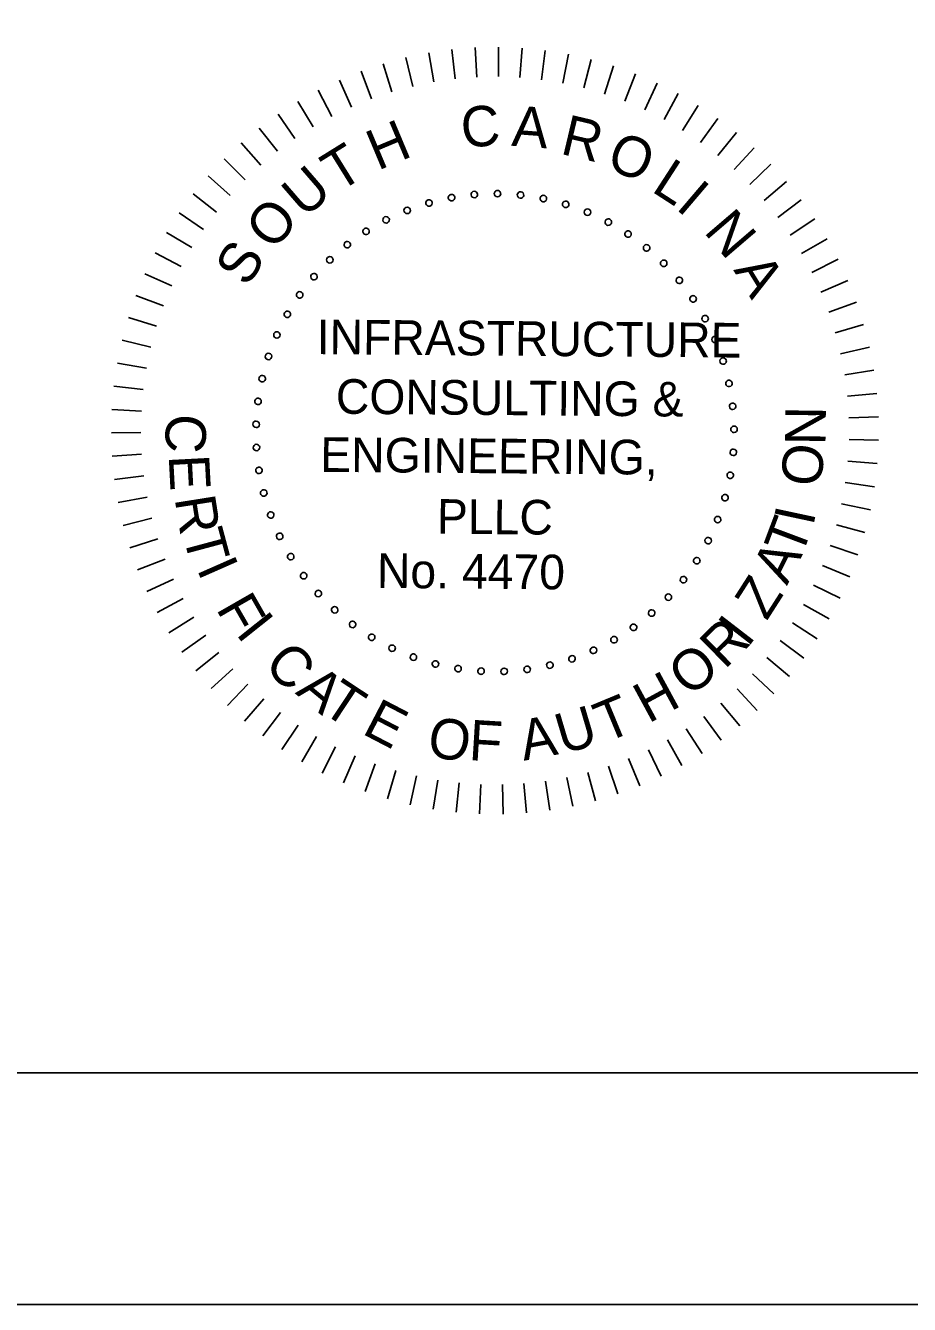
# Model space of a CAD drawing. Extents: x -125.5 to -89.4, y -5.1 to 16.9.
# Drawn here: x -100.213 to -98.306, y -5.066 to -2.306 of the extents above; entities that cross this region are included whole.
import ezdxf

# ---------------------------------------------------------------- set-up
doc = ezdxf.new("R2010")
doc.units = 0
for name, color, linetype in [('BR_BORDER LINES', 7, 'Continuous'), ('BR_TEXT', 7, 'Continuous'), ('Level 31', 7, 'Continuous')]:
    doc.layers.add(name, color=color, linetype=linetype)

msp = doc.modelspace()

# ---------------------------------------------------------------- linework, layer by layer
at = {"layer": 'BR_BORDER LINES'}
msp.add_line((-123.6994, -4.5662), (-90.0334, -4.5662), dxfattribs=at)
at = {"layer": 'BR_TEXT'}
for p, q in [((-99.343, -2.3651), (-99.332, -2.4278)), ((-99.2931, -2.3579), (-99.2858, -2.4212)), ((-99.2427, -2.3538), (-99.2394, -2.4174)), ((-99.1923, -2.3527), (-99.1928, -2.4164)), ((-99.1418, -2.3548), (-99.1462, -2.4183)), ((-99.0916, -2.3599), (-99.0999, -2.423)), ((-99.0418, -2.368), (-99.0539, -2.4305)), ((-99.4412, -2.3886), (-99.4226, -2.4495)), ((-99.3925, -2.3754), (-99.3776, -2.4373)), ((-98.9925, -2.3792), (-99.0084, -2.4408)), ((-98.9441, -2.3933), (-98.9637, -2.4539)), ((-99.5358, -2.4238), (-99.5099, -2.482)), ((-99.489, -2.4048), (-99.4667, -2.4644)), ((-98.8966, -2.4104), (-98.9199, -2.4696)), ((-99.5813, -2.4457), (-99.5519, -2.5022)), ((-98.8502, -2.4303), (-98.877, -2.488)), ((-98.8051, -2.453), (-98.8354, -2.509)), ((-99.6253, -2.4703), (-99.5926, -2.5249)), ((-98.7615, -2.4785), (-98.7952, -2.5325)), ((-99.6678, -2.4975), (-99.6318, -2.55)), ((-98.7195, -2.5065), (-98.7564, -2.5584)), ((-99.7086, -2.5273), (-99.6694, -2.5775)), ((-98.6793, -2.5371), (-98.7193, -2.5866)), ((-99.7475, -2.5595), (-99.7053, -2.6072)), ((-99.7843, -2.5941), (-99.7393, -2.6391)), ((-98.6411, -2.57), (-98.684, -2.617)), ((-98.6049, -2.6052), (-98.6506, -2.6495)), ((-99.819, -2.6308), (-99.7713, -2.673)), ((-98.571, -2.6426), (-98.6193, -2.684)), ((-99.8513, -2.6695), (-99.8012, -2.7087)), ((-98.5393, -2.6819), (-98.5901, -2.7204)), ((-99.8813, -2.7102), (-99.8288, -2.7463)), ((-98.5102, -2.7232), (-98.5632, -2.7584)), ((-99.9087, -2.7526), (-99.8541, -2.7854)), ((-98.4836, -2.7661), (-98.5387, -2.798)), ((-99.9334, -2.7965), (-99.877, -2.826)), ((-98.4597, -2.8105), (-98.5166, -2.839)), ((-99.9555, -2.842), (-99.8973, -2.8679)), ((-98.4385, -2.8563), (-98.497, -2.8813)), ((-99.9747, -2.8886), (-99.9151, -2.911)), ((-98.4202, -2.9034), (-98.4801, -2.9248)), ((-99.991, -2.9364), (-99.9302, -2.9551)), ((-98.4047, -2.9514), (-98.4659, -2.9691)), ((-100.0044, -2.9851), (-99.9426, -3)), ((-98.3922, -3.0004), (-98.4544, -3.0143)), ((-100.0149, -3.0345), (-99.9522, -3.0456)), ((-98.3828, -3.05), (-98.4456, -3.0601)), ((-100.0222, -3.0844), (-99.959, -3.0917)), ((-98.3763, -3.1), (-98.4397, -3.1063)), ((-100.0266, -3.1347), (-99.963, -3.1382)), ((-98.373, -3.1504), (-98.4366, -3.1528)), ((-100.0278, -3.1852), (-99.9641, -3.1847)), ((-98.3727, -3.2009), (-98.4363, -3.1994)), ((-100.026, -3.2356), (-99.9625, -3.2313)), ((-98.3755, -3.2513), (-98.4389, -3.2459)), ((-100.0211, -3.2859), (-99.9579, -3.2777)), ((-98.3813, -3.3014), (-98.4443, -3.2922)), ((-100.0131, -3.3357), (-99.9506, -3.3237)), ((-98.3902, -3.3511), (-98.4525, -3.3381)), ((-100.0021, -3.385), (-99.9405, -3.3692)), ((-98.4021, -3.4002), (-98.4635, -3.3834)), ((-99.9882, -3.4335), (-99.9276, -3.414)), ((-98.417, -3.4484), (-98.4773, -3.4279)), ((-99.9713, -3.4811), (-99.912, -3.4579)), ((-98.4348, -3.4957), (-98.4937, -3.4715)), ((-99.9515, -3.5276), (-99.8937, -3.5008)), ((-98.4554, -3.5417), (-98.5128, -3.514)), ((-99.929, -3.5727), (-99.8729, -3.5425)), ((-98.4789, -3.5865), (-98.5344, -3.5553)), ((-99.9037, -3.6164), (-99.8496, -3.5828)), ((-98.505, -3.6297), (-98.5585, -3.5952)), ((-99.8758, -3.6585), (-99.8239, -3.6217)), ((-98.5336, -3.6712), (-98.5849, -3.6335)), ((-99.8454, -3.6988), (-99.7958, -3.6589)), ((-98.5648, -3.7109), (-98.6137, -3.6702)), ((-99.8126, -3.7372), (-99.7655, -3.6943)), ((-98.5983, -3.7487), (-98.6447, -3.705)), ((-99.7775, -3.7735), (-99.7331, -3.7278)), ((-98.6341, -3.7843), (-98.6777, -3.7379)), ((-99.7403, -3.8076), (-99.6988, -3.7593)), ((-98.672, -3.8177), (-98.7126, -3.7687)), ((-99.701, -3.8393), (-99.6626, -3.7886)), ((-98.7118, -3.8487), (-98.7494, -3.7974)), ((-99.6599, -3.8687), (-99.6246, -3.8157)), ((-98.7534, -3.8772), (-98.7879, -3.8237)), ((-99.6171, -3.8954), (-99.5851, -3.8404)), ((-99.5728, -3.9195), (-99.5442, -3.8626)), ((-98.7967, -3.9032), (-98.8278, -3.8476)), ((-99.527, -3.9408), (-99.5019, -3.8823)), ((-98.8877, -3.9469), (-98.9118, -3.888)), ((-98.8416, -3.9264), (-98.8692, -3.8691)), ((-99.48, -3.9594), (-99.4586, -3.8994)), ((-99.432, -3.975), (-99.4143, -3.9138)), ((-98.9833, -3.9792), (-99.0001, -3.9178)), ((-98.935, -3.9645), (-98.9555, -3.9042)), ((-99.3832, -3.9876), (-99.3692, -3.9255)), ((-99.3336, -3.9973), (-99.3234, -3.9344)), ((-99.2836, -4.0039), (-99.2772, -3.9406)), ((-99.2332, -4.0075), (-99.2307, -3.9438)), ((-99.1827, -4.0079), (-99.1841, -3.9443)), ((-99.1323, -4.0053), (-99.1376, -3.9419)), ((-99.0821, -3.9997), (-99.0913, -3.9367)), ((-99.0324, -3.991), (-99.0454, -3.9286))]:
    msp.add_line(p, q, dxfattribs=at)
for centre, start, end in [((-99.2939, -2.6775), 10.6038, 190.6038), ((-99.2939, -2.6775), 190.6038, 10.6038), ((-99.2445, -2.6708), 5.0653, 185.0653), ((-99.2445, -2.6708), 185.0653, 5.0653), ((-99.1947, -2.6689), 359.5268, 179.5268), ((-99.1947, -2.6689), 179.5268, 359.5268), ((-99.145, -2.6718), 173.9884, 353.9884), ((-99.145, -2.6718), 353.9884, 173.9884), ((-99.0957, -2.6795), 348.4499, 168.4499), ((-99.3896, -2.705), 21.6807, 201.6807), ((-99.3896, -2.705), 201.6807, 21.6807), ((-99.3424, -2.6889), 16.1422, 196.1422), ((-99.3424, -2.6889), 196.1422, 16.1422), ((-99.0957, -2.6795), 168.4499, 348.4499), ((-99.0475, -2.6919), 162.9114, 342.9114), ((-99.0475, -2.6919), 342.9114, 162.9114), ((-99.0006, -2.709), 337.373, 157.373), ((-99.435, -2.7255), 27.2191, 207.2191), ((-99.435, -2.7255), 207.2191, 27.2191), ((-99.0006, -2.709), 157.373, 337.373), ((-98.9557, -2.7304), 151.8345, 331.8345), ((-98.9557, -2.7304), 331.8345, 151.8345), ((-99.4782, -2.7503), 32.7576, 212.7576), ((-99.4782, -2.7503), 212.7576, 32.7576), ((-98.913, -2.7561), 146.2961, 326.2961), ((-98.913, -2.7561), 326.2961, 146.2961), ((-99.5188, -2.7792), 38.2961, 218.2961), ((-99.5188, -2.7792), 218.2961, 38.2961), ((-98.873, -2.7858), 140.7576, 320.7576), ((-98.873, -2.7858), 320.7576, 140.7576), ((-99.5564, -2.8119), 43.8345, 223.8345), ((-99.5564, -2.8119), 223.8345, 43.8345), ((-98.836, -2.8192), 135.2191, 315.2191), ((-98.836, -2.8192), 315.2191, 135.2191), ((-99.5907, -2.848), 49.373, 229.373), ((-99.5907, -2.848), 229.373, 49.373), ((-98.8024, -2.8561), 129.6807, 309.6807), ((-98.8024, -2.8561), 309.6807, 129.6807), ((-99.6214, -2.8873), 54.9114, 234.9114), ((-99.6214, -2.8873), 234.9114, 54.9114), ((-98.7726, -2.896), 124.1422, 304.1422), ((-98.7726, -2.896), 304.1422, 124.1422), ((-99.6481, -2.9293), 60.4499, 240.4499), ((-99.6481, -2.9293), 240.4499, 60.4499), ((-98.7467, -2.9386), 118.6038, 298.6038), ((-98.7467, -2.9386), 298.6038, 118.6038), ((-99.6706, -2.9738), 65.9884, 245.9884), ((-99.6706, -2.9738), 245.9884, 65.9884), ((-98.7251, -2.9835), 113.0653, 293.0653), ((-98.7251, -2.9835), 293.0653, 113.0653), ((-99.6888, -3.0202), 71.5268, 251.5268), ((-99.6888, -3.0202), 251.5268, 71.5268), ((-98.7079, -3.0302), 107.5268, 287.5268), ((-98.7079, -3.0302), 287.5268, 107.5268), ((-99.7024, -3.0681), 77.0653, 257.0653), ((-99.7024, -3.0681), 257.0653, 77.0653), ((-98.6953, -3.0785), 101.9884, 281.9884), ((-98.6953, -3.0785), 281.9884, 101.9884), ((-99.7113, -3.1172), 82.6038, 262.6038), ((-99.7113, -3.1172), 262.6038, 82.6038), ((-98.6874, -3.1277), 96.4499, 276.4499), ((-98.6874, -3.1277), 276.4499, 96.4499), ((-99.7154, -3.1668), 88.1422, 268.1422), ((-99.7154, -3.1668), 268.1422, 88.1422), ((-98.6843, -3.1774), 90.9114, 270.9114), ((-98.6843, -3.1774), 270.9114, 90.9114), ((-99.7147, -3.2167), 93.6807, 273.6807), ((-99.7147, -3.2167), 273.6807, 93.6807), ((-98.686, -3.2272), 85.373, 265.373), ((-98.686, -3.2272), 265.373, 85.373), ((-99.7092, -3.2662), 99.2191, 279.2191), ((-99.7092, -3.2662), 279.2191, 99.2191), ((-98.6926, -3.2766), 79.8345, 259.8345), ((-98.6926, -3.2766), 259.8345, 79.8345), ((-99.6989, -3.3149), 104.7576, 284.7576), ((-99.6989, -3.3149), 284.7576, 104.7576), ((-98.7038, -3.3251), 74.2961, 254.2961), ((-98.7038, -3.3251), 254.2961, 74.2961), ((-99.684, -3.3625), 110.2961, 290.2961), ((-99.684, -3.3625), 290.2961, 110.2961), ((-98.7197, -3.3724), 68.7576, 248.7576), ((-98.7197, -3.3724), 248.7576, 68.7576), ((-99.6646, -3.4084), 115.8345, 295.8345), ((-99.6646, -3.4084), 295.8345, 115.8345), ((-98.7401, -3.4178), 63.2191, 243.2191), ((-98.7401, -3.4178), 243.2191, 63.2191), ((-99.6408, -3.4522), 121.373, 301.373), ((-99.6408, -3.4522), 301.373, 121.373), ((-98.7647, -3.4611), 57.6807, 237.6807), ((-98.7647, -3.4611), 237.6807, 57.6807), ((-99.6129, -3.4935), 126.9114, 306.9114), ((-99.6129, -3.4935), 306.9114, 126.9114), ((-98.7934, -3.5019), 52.1422, 232.1422), ((-98.7934, -3.5019), 232.1422, 52.1422), ((-99.5812, -3.5319), 132.4499, 312.4499), ((-99.5812, -3.5319), 312.4499, 132.4499), ((-98.826, -3.5396), 46.6038, 226.6038), ((-99.5459, -3.5671), 317.9884, 137.9884), ((-98.826, -3.5396), 226.6038, 46.6038), ((-99.5459, -3.5671), 137.9884, 317.9884), ((-98.862, -3.5741), 41.0653, 221.0653), ((-98.862, -3.5741), 221.0653, 41.0653), ((-99.5074, -3.5987), 143.5268, 323.5268), ((-99.5074, -3.5987), 323.5268, 143.5268), ((-98.9012, -3.6049), 35.5268, 215.5268), ((-98.9012, -3.6049), 215.5268, 35.5268), ((-99.466, -3.6264), 149.0653, 329.0653), ((-99.466, -3.6264), 329.0653, 149.0653), ((-99.4221, -3.65), 334.6038, 154.6038), ((-98.9431, -3.6317), 29.9884, 209.9884), ((-98.9431, -3.6317), 209.9884, 29.9884), ((-99.4221, -3.65), 154.6038, 334.6038), ((-99.3761, -3.6693), 160.1422, 340.1422), ((-99.3761, -3.6693), 340.1422, 160.1422), ((-99.0338, -3.6728), 18.9114, 198.9114), ((-99.0338, -3.6728), 198.9114, 18.9114), ((-98.9875, -3.6545), 24.4499, 204.4499), ((-98.9875, -3.6545), 204.4499, 24.4499), ((-99.3285, -3.684), 165.6807, 345.6807), ((-99.3285, -3.684), 345.6807, 165.6807), ((-99.2797, -3.6941), 351.2191, 171.2191), ((-99.2797, -3.6941), 171.2191, 351.2191), ((-99.2302, -3.6994), 356.7576, 176.7576), ((-99.1803, -3.6999), 2.2961, 182.2961), ((-99.1307, -3.6956), 7.8345, 187.8345), ((-99.1307, -3.6956), 187.8345, 7.8345), ((-99.0817, -3.6865), 13.373, 193.373), ((-99.0817, -3.6865), 193.373, 13.373), ((-99.2302, -3.6994), 176.7576, 356.7576), ((-99.1803, -3.6999), 182.2961, 2.2961)]:
    msp.add_arc(centre, 0.00701, start, end, dxfattribs=at)
at = {"layer": 'Level 31'}
msp.add_lwpolyline([(-125.5328, 16.9339), (-125.5328, -5.0661), (-89.5328, -5.0661), (-89.5328, 16.9339)], dxfattribs=at)

# ---------------------------------------------------------------- texts
at = {"layer": 'BR_TEXT'}
for s, height, rotation, p in [('C', 0.0872, 4.7281, (-99.2702, -2.5703)), ('A', 0.0872, 355.6981, (-99.1657, -2.5654)), ('H', 0.0872, 22.7882, (-99.453, -2.6197)), ('R', 0.0872, 346.6681, (-99.0615, -2.5824)), ('T', 0.0872, 31.8182, (-99.5379, -2.6674)), ('O', 0.0872, 337.638, (-98.9637, -2.6122)), ('U', 0.0872, 40.8482, (-99.6112, -2.7235)), ('L', 0.0872, 327.108, (-98.8649, -2.6626)), ('I', 0.0872, 319.578, (-98.8123, -2.7005)), ('O', 0.0872, 49.8782, (-99.6782, -2.7945)), ('N', 0.0872, 310.548, (-98.7515, -2.7512)), ('S', 0.0872, 58.9083, (-99.7336, -2.8727)), ('A', 0.0872, 301.5179, (-98.6864, -2.8336)), ('INFRASTRUCTURE', 0.074771, 359.5268, (-99.585, -3.0152)), ('CONSULTING &', 0.074771, 359.5268, (-99.5437, -3.1438)), ('N', 0.0872, 89.2085, (-98.4872, -3.2124)), ('C', 0.0872, 267.025, (-99.9086, -3.1426)), ('ENGINEERING,', 0.074771, 359.5268, (-99.5773, -3.2693)), ('O', 0.0872, 83.2085, (-98.4982, -3.3038)), ('E', 0.0872, 273.025, (-99.9042, -3.2342)), ('R', 0.0872, 279.025, (-99.8914, -3.3265)), ('PLLC', 0.07477, 359.5268, (-99.3256, -3.4028)), ('T', 0.0872, 69.3954, (-98.5394, -3.4556)), ('I', 0.0872, 77.9093, (-98.5137, -3.3881)), ('T', 0.0872, 285.025, (-99.874, -3.4053)), ('No. 4470', 0.07477, 359.5268, (-99.4551, -3.5197)), ('A', 0.0872, 63.3954, (-98.5702, -3.516)), ('I', 0.0872, 293.7713, (-99.8443, -3.4784)), ('Z', 0.0872, 57.3954, (-98.6141, -3.5923)), ('F', 0.0872, 299.7713, (-99.8031, -3.5644)), ('I', 0.0872, 308.5268, (-99.761, -3.6183)), ('I', 0.0872, 52.3339, (-98.6551, -3.65)), ('R', 0.0872, 44.5268, (-98.7045, -3.6973)), ('C', 0.0872, 314.5268, (-99.7017, -3.6884)), ('O', 0.0872, 38.5268, (-98.7811, -3.7572)), ('A', 0.0872, 320.5268, (-99.6325, -3.747)), ('T', 0.0872, 326.5268, (-99.5781, -3.7855)), ('H', 0.0872, 28.5268, (-98.8692, -3.8132)), ('T', 0.0872, 22.5268, (-98.9624, -3.855)), ('E', 0.0872, 332.5268, (-99.4895, -3.8332)), ('U', 0.0872, 16.5268, (-99.0541, -3.8794)), ('O', 0.0872, 350.5268, (-99.3494, -3.8821)), ('F', 0.0872, 356.5268, (-99.2579, -3.8912)), ('A', 0.0872, 10.5268, (-99.138, -3.8929))]:
    msp.add_text(s, height=height, rotation=rotation, dxfattribs=at).set_placement(p)

doc.saveas('drawing.dxf')
